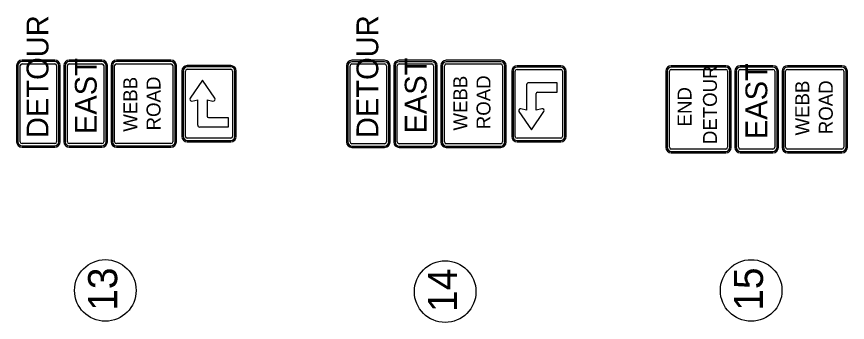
# Model space of a CAD drawing. Extents: x 1123038 to 1172987, y 554419 to 623636.
# Drawn here: x 1129459 to 1134226, y 558025 to 559782 of the extents above; entities that cross this region are included whole.
import ezdxf

# ---------------------------------------------------------------- set-up
doc = ezdxf.new("R2010")
doc.units = 0
doc.layers.add('D_Text_Standard', color=7, linetype='Continuous')
doc.layers.add('Default', color=7, linetype='Continuous')

msp = doc.modelspace()

# ---------------------------------------------------------------- linework, layer by layer
at = {"layer": 'D_Text_Standard'}
for centre in [(1129968.3, 558209), (1131918.2, 558202.3), (1133674, 558208.9)]:
    msp.add_circle(centre, 176.8, dxfattribs=at)
at = {"layer": 'Default'}
for p, q in [((1129677.9, 559531.6), (1129490.4, 559531.6)), ((1129677.9, 559523.8), (1129490.4, 559523.8)), ((1129490.4, 559510.8), (1129677.9, 559510.8)), ((1129948.7, 559531.6), (1129761.2, 559531.6)), ((1129948.7, 559523.8), (1129761.2, 559523.8)), ((1129761.2, 559510.8), (1129948.7, 559510.8)), ((1130344.6, 559531.6), (1130032.1, 559531.6)), ((1130344.6, 559523.8), (1130032.1, 559523.8)), ((1130032.1, 559510.8), (1130344.6, 559510.8)), ((1131570.7, 559530.8), (1131383.2, 559530.8)), ((1131570.7, 559523), (1131383.2, 559523)), ((1131383.2, 559510), (1131570.7, 559510)), ((1131841.5, 559530.8), (1131654, 559530.8)), ((1131841.5, 559523), (1131654, 559523)), ((1131654, 559510), (1131841.5, 559510)), ((1132237.3, 559530.8), (1131924.8, 559530.8)), ((1132237.3, 559523), (1131924.8, 559523)), ((1131924.8, 559510), (1132237.3, 559510)), ((1129459.2, 559500.3), (1129459.2, 559062.9)), ((1129467, 559500.3), (1129467, 559062.9)), ((1129480, 559062.9), (1129480, 559500.3)), ((1129688.3, 559500.3), (1129688.3, 559062.9)), ((1129701.3, 559062.9), (1129701.3, 559500.3)), ((1129709.2, 559062.9), (1129709.2, 559500.3)), ((1129730, 559500.3), (1129730, 559062.9)), ((1129737.8, 559500.3), (1129737.8, 559062.9)), ((1129750.8, 559062.9), (1129750.8, 559500.3)), ((1129959.2, 559500.3), (1129959.2, 559062.9)), ((1129972.2, 559062.9), (1129972.2, 559500.3)), ((1129980, 559062.9), (1129980, 559500.3)), ((1130000.8, 559500.3), (1130000.8, 559062.9)), ((1130008.6, 559500.3), (1130008.6, 559062.9)), ((1130021.7, 559062.9), (1130021.7, 559500.3)), ((1130355, 559500.3), (1130355, 559062.9)), ((1130368, 559062.9), (1130368, 559500.3)), ((1130375.8, 559062.9), (1130375.8, 559500.3)), ((1130407.1, 559469.1), (1130407.1, 559094.1)), ((1130414.9, 559469.1), (1130414.9, 559094.1)), ((1130427.9, 559094.1), (1130427.9, 559469.1)), ((1130688.3, 559500.3), (1130438.3, 559500.3)), ((1130688.3, 559492.5), (1130438.3, 559492.5)), ((1130438.3, 559479.5), (1130688.3, 559479.5)), ((1130698.7, 559469.1), (1130698.7, 559094.1)), ((1130711.8, 559094.1), (1130711.8, 559469.1)), ((1130719.6, 559094.1), (1130719.6, 559469.1)), ((1131351.9, 559499.5), (1131351.9, 559062)), ((1131359.7, 559499.5), (1131359.7, 559062)), ((1131372.8, 559062), (1131372.8, 559499.5)), ((1131581.1, 559499.5), (1131581.1, 559062)), ((1131594.1, 559062), (1131594.1, 559499.5)), ((1131601.9, 559062), (1131601.9, 559499.5)), ((1131622.8, 559499.5), (1131622.8, 559062)), ((1131630.6, 559499.5), (1131630.6, 559062)), ((1131643.6, 559062), (1131643.6, 559499.5)), ((1131851.9, 559499.5), (1131851.9, 559062)), ((1131865, 559062), (1131865, 559499.5)), ((1131872.8, 559062), (1131872.8, 559499.5)), ((1131893.6, 559499.5), (1131893.6, 559062)), ((1131901.4, 559499.5), (1131901.4, 559062)), ((1131914.4, 559062), (1131914.4, 559499.5)), ((1132247.8, 559499.5), (1132247.8, 559062)), ((1132260.8, 559062), (1132260.8, 559499.5)), ((1132268.6, 559062), (1132268.6, 559499.5)), ((1132299.8, 559468.3), (1132299.8, 559093.3)), ((1132307.7, 559468.3), (1132307.7, 559093.3)), ((1132320.7, 559093.3), (1132320.7, 559468.3)), ((1132581.1, 559499.5), (1132331.1, 559499.5)), ((1132581.1, 559491.7), (1132331.1, 559491.7)), ((1132331.1, 559478.7), (1132581.1, 559478.7)), ((1132591.5, 559468.3), (1132591.5, 559093.3)), ((1132604.5, 559093.3), (1132604.5, 559468.3)), ((1132612.3, 559093.3), (1132612.3, 559468.3)), ((1133184.5, 559468.5), (1133184.5, 559031)), ((1133192.3, 559468.5), (1133192.3, 559031)), ((1133205.3, 559031), (1133205.3, 559468.5)), ((1133528.2, 559499.7), (1133215.7, 559499.7)), ((1133528.2, 559491.9), (1133215.7, 559491.9)), ((1133215.7, 559478.9), (1133528.2, 559478.9)), ((1133538.7, 559468.5), (1133538.7, 559031)), ((1133551.7, 559031), (1133551.7, 559468.5)), ((1133559.5, 559031), (1133559.5, 559468.5)), ((1133580.3, 559468.5), (1133580.3, 559031)), ((1133588.1, 559468.5), (1133588.1, 559031)), ((1133601.2, 559031), (1133601.2, 559468.5)), ((1133799.1, 559499.7), (1133611.6, 559499.7)), ((1133799.1, 559491.9), (1133611.6, 559491.9)), ((1133611.6, 559478.9), (1133799.1, 559478.9)), ((1133809.5, 559468.5), (1133809.5, 559031)), ((1133822.5, 559031), (1133822.5, 559468.5)), ((1133830.3, 559031), (1133830.3, 559468.5)), ((1133851.2, 559468.5), (1133851.2, 559031)), ((1133859, 559468.5), (1133859, 559031)), ((1133872, 559031), (1133872, 559468.5)), ((1134194.9, 559499.7), (1133882.4, 559499.7)), ((1134194.9, 559491.9), (1133882.4, 559491.9)), ((1133882.4, 559478.9), (1134194.9, 559478.9)), ((1134205.3, 559468.5), (1134205.3, 559031)), ((1134218.3, 559031), (1134218.3, 559468.5)), ((1134226.2, 559031), (1134226.2, 559468.5)), ((1130525.6, 559416.4), (1130454.3, 559312.6)), ((1130596.9, 559312.6), (1130525.6, 559416.4)), ((1132385.8, 559390.2), (1132385.8, 559244.3)), ((1132561.6, 559401.9), (1132397.5, 559401.9)), ((1132561.6, 559347.2), (1132561.6, 559401.9)), ((1132440.5, 559244.3), (1132440.5, 559339.4)), ((1132448.3, 559347.2), (1132561.6, 559347.2)), ((1130465.4, 559296.8), (1130498.2, 559304.4)), ((1130498.2, 559158.6), (1130498.2, 559304.4)), ((1130552.9, 559304.4), (1130585.7, 559296.8)), ((1130552.9, 559304.4), (1130552.9, 559209.3)), ((1132341.8, 559236.2), (1132413.1, 559132.4)), ((1132385.8, 559244.3), (1132353, 559251.9)), ((1132413.1, 559132.4), (1132484.4, 559236.2)), ((1132473.3, 559251.9), (1132440.5, 559244.3)), ((1130560.7, 559201.5), (1130674, 559201.5)), ((1130674, 559201.5), (1130674, 559146.8)), ((1130674, 559146.8), (1130509.9, 559146.8)), ((1130688.3, 559083.7), (1130438.3, 559083.7)), ((1132581.1, 559082.9), (1132331.1, 559082.9)), ((1129677.9, 559052.4), (1129490.4, 559052.4)), ((1129490.4, 559039.4), (1129677.9, 559039.4)), ((1129490.4, 559031.6), (1129677.9, 559031.6)), ((1129948.7, 559052.4), (1129761.2, 559052.4)), ((1129761.2, 559039.4), (1129948.7, 559039.4)), ((1129761.2, 559031.6), (1129948.7, 559031.6)), ((1130344.6, 559052.4), (1130032.1, 559052.4)), ((1130032.1, 559039.4), (1130344.6, 559039.4)), ((1130032.1, 559031.6), (1130344.6, 559031.6)), ((1130438.3, 559070.7), (1130688.3, 559070.7)), ((1130438.3, 559062.9), (1130688.3, 559062.9)), ((1131570.7, 559051.6), (1131383.2, 559051.6)), ((1131383.2, 559038.6), (1131570.7, 559038.6)), ((1131383.2, 559030.8), (1131570.7, 559030.8)), ((1131841.5, 559051.6), (1131654, 559051.6)), ((1131654, 559038.6), (1131841.5, 559038.6)), ((1131654, 559030.8), (1131841.5, 559030.8)), ((1132237.3, 559051.6), (1131924.8, 559051.6)), ((1131924.8, 559038.6), (1132237.3, 559038.6)), ((1131924.8, 559030.8), (1132237.3, 559030.8)), ((1132331.1, 559069.9), (1132581.1, 559069.9)), ((1132331.1, 559062), (1132581.1, 559062)), ((1133528.2, 559020.6), (1133215.7, 559020.6)), ((1133215.7, 559007.5), (1133528.2, 559007.5)), ((1133215.7, 558999.7), (1133528.2, 558999.7)), ((1133799.1, 559020.6), (1133611.6, 559020.6)), ((1133611.6, 559007.5), (1133799.1, 559007.5)), ((1133611.6, 558999.7), (1133799.1, 558999.7)), ((1134194.9, 559020.6), (1133882.4, 559020.6)), ((1133882.4, 559007.5), (1134194.9, 559007.5)), ((1133882.4, 558999.7), (1134194.9, 558999.7))]:
    msp.add_line(p, q, dxfattribs=at)
for centre, radius, start, end in [((1129490.4, 559500.3), 31.2, 90, 180), ((1129490.4, 559500.3), 23.4, 90, 180), ((1129490.4, 559500.3), 10.4, 90, 180), ((1129677.9, 559500.3), 31.2, 0, 90), ((1129677.9, 559500.3), 23.4, 0, 90), ((1129677.9, 559500.3), 10.4, 0, 90), ((1129761.2, 559500.3), 31.2, 90, 180), ((1129761.2, 559500.3), 23.4, 90, 180), ((1129761.2, 559500.3), 10.4, 90, 180), ((1129948.7, 559500.3), 31.2, 0, 90), ((1129948.7, 559500.3), 23.4, 0, 90), ((1129948.7, 559500.3), 10.4, 0, 90), ((1130032.1, 559500.3), 31.2, 90, 180), ((1130032.1, 559500.3), 23.4, 90, 180), ((1130032.1, 559500.3), 10.4, 90, 180), ((1130344.6, 559500.3), 31.2, 0, 90), ((1130344.6, 559500.3), 23.4, 0, 90), ((1130344.6, 559500.3), 10.4, 0, 90), ((1131383.2, 559499.5), 31.2, 90, 180), ((1131383.2, 559499.5), 23.4, 90, 180), ((1131383.2, 559499.5), 10.4, 90, 180), ((1131570.7, 559499.5), 31.2, 0, 90), ((1131570.7, 559499.5), 23.4, 0, 90), ((1131570.7, 559499.5), 10.4, 0, 90), ((1131654, 559499.5), 31.2, 90, 180), ((1131654, 559499.5), 23.4, 90, 180), ((1131654, 559499.5), 10.4, 90, 180), ((1131841.5, 559499.5), 31.2, 0, 90), ((1131841.5, 559499.5), 23.4, 0, 90), ((1131841.5, 559499.5), 10.4, 0, 90), ((1131924.8, 559499.5), 31.2, 90, 180), ((1131924.8, 559499.5), 23.4, 90, 180), ((1131924.8, 559499.5), 10.4, 90, 180), ((1132237.3, 559499.5), 31.2, 0, 90), ((1132237.3, 559499.5), 23.4, 0, 90), ((1132237.3, 559499.5), 10.4, 0, 90), ((1130438.3, 559469.1), 31.2, 90, 180), ((1130438.3, 559469.1), 23.4, 90, 180), ((1130438.3, 559469.1), 10.4, 90, 180), ((1130688.3, 559469.1), 31.2, 0, 90), ((1130688.3, 559469.1), 23.4, 0, 90), ((1130688.3, 559469.1), 10.4, 0, 90), ((1132331.1, 559468.3), 31.2, 90, 180), ((1132331.1, 559468.3), 23.4, 90, 180), ((1132331.1, 559468.3), 10.4, 90, 180), ((1132581.1, 559468.3), 31.2, 0, 90), ((1132581.1, 559468.3), 23.4, 0, 90), ((1132581.1, 559468.3), 10.4, 0, 90), ((1133215.7, 559468.5), 31.2, 90, 180), ((1133215.7, 559468.5), 23.4, 90, 180), ((1133215.7, 559468.5), 10.4, 90, 180), ((1133528.2, 559468.5), 31.2, 0, 90), ((1133528.2, 559468.5), 23.4, 0, 90), ((1133528.2, 559468.5), 10.4, 0, 90), ((1133611.6, 559468.5), 31.2, 90, 180), ((1133611.6, 559468.5), 23.4, 90, 180), ((1133611.6, 559468.5), 10.4, 90, 180), ((1133799.1, 559468.5), 31.2, 0, 90), ((1133799.1, 559468.5), 23.4, 0, 90), ((1133799.1, 559468.5), 10.4, 0, 90), ((1133882.4, 559468.5), 31.2, 90, 180), ((1133882.4, 559468.5), 23.4, 90, 180), ((1133882.4, 559468.5), 10.4, 90, 180), ((1134194.9, 559468.5), 31.2, 0, 90), ((1134194.9, 559468.5), 23.4, 0, 90), ((1134194.9, 559468.5), 10.4, 0, 90), ((1132397.5, 559390.2), 11.7, 90, 180), ((1130463.1, 559307), 10.4, 147.7244, 282.9503), ((1130588.1, 559307), 10.4, 257.0497, 32.2757), ((1132448.3, 559339.4), 7.81, 90, 180), ((1132350.6, 559241.7), 10.4, 77.0497, 212.2757), ((1132475.6, 559241.7), 10.4, 327.7244, 102.9504), ((1130560.7, 559209.3), 7.81, 180, 270), ((1130509.9, 559158.6), 11.7, 180, 270), ((1130438.3, 559094.1), 31.2, 180, 270), ((1130438.3, 559094.1), 23.4, 180, 270), ((1130438.3, 559094.1), 10.4, 180, 270), ((1130688.3, 559094.1), 31.2, 270, 0), ((1130688.3, 559094.1), 23.4, 270, 0), ((1130688.3, 559094.1), 10.4, 270, 0), ((1132331.1, 559093.3), 31.2, 180, 270), ((1132331.1, 559093.3), 23.4, 180, 270), ((1132331.1, 559093.3), 10.4, 180, 270), ((1132581.1, 559093.3), 31.2, 270, 0), ((1132581.1, 559093.3), 23.4, 270, 0), ((1132581.1, 559093.3), 10.4, 270, 0), ((1129490.4, 559062.9), 31.2, 180, 270), ((1129490.4, 559062.9), 23.4, 180, 270), ((1129490.4, 559062.9), 10.4, 180, 270), ((1129677.9, 559062.9), 31.2, 270, 0), ((1129677.9, 559062.9), 23.4, 270, 0), ((1129677.9, 559062.9), 10.4, 270, 0), ((1129761.2, 559062.9), 31.2, 180, 270), ((1129761.2, 559062.9), 23.4, 180, 270), ((1129761.2, 559062.9), 10.4, 180, 270), ((1129948.7, 559062.9), 31.2, 270, 0), ((1129948.7, 559062.9), 23.4, 270, 0), ((1129948.7, 559062.9), 10.4, 270, 0), ((1130032.1, 559062.9), 31.2, 180, 270), ((1130032.1, 559062.9), 23.4, 180, 270), ((1130032.1, 559062.9), 10.4, 180, 270), ((1130344.6, 559062.9), 31.2, 270, 0), ((1130344.6, 559062.9), 23.4, 270, 0), ((1130344.6, 559062.9), 10.4, 270, 0), ((1131383.2, 559062), 31.2, 180, 270), ((1131383.2, 559062), 23.4, 180, 270), ((1131383.2, 559062), 10.4, 180, 270), ((1131570.7, 559062), 31.2, 270, 0), ((1131570.7, 559062), 23.4, 270, 0), ((1131570.7, 559062), 10.4, 270, 0), ((1131654, 559062), 31.2, 180, 270), ((1131654, 559062), 23.4, 180, 270), ((1131654, 559062), 10.4, 180, 270), ((1131841.5, 559062), 31.2, 270, 0), ((1131841.5, 559062), 23.4, 270, 0), ((1131841.5, 559062), 10.4, 270, 0), ((1131924.8, 559062), 31.2, 180, 270), ((1131924.8, 559062), 23.4, 180, 270), ((1131924.8, 559062), 10.4, 180, 270), ((1132237.3, 559062), 31.2, 270, 0), ((1132237.3, 559062), 23.4, 270, 0), ((1132237.3, 559062), 10.4, 270, 0), ((1133215.7, 559031), 31.2, 180, 270), ((1133215.7, 559031), 23.4, 180, 270), ((1133215.7, 559031), 10.4, 180, 270), ((1133528.2, 559031), 31.2, 270, 0), ((1133528.2, 559031), 23.4, 270, 0), ((1133528.2, 559031), 10.4, 270, 0), ((1133611.6, 559031), 31.2, 180, 270), ((1133611.6, 559031), 23.4, 180, 270), ((1133611.6, 559031), 10.4, 180, 270), ((1133799.1, 559031), 31.2, 270, 0), ((1133799.1, 559031), 23.4, 270, 0), ((1133799.1, 559031), 10.4, 270, 0), ((1133882.4, 559031), 31.2, 180, 270), ((1133882.4, 559031), 23.4, 180, 270), ((1133882.4, 559031), 10.4, 180, 270), ((1134194.9, 559031), 31.2, 270, 0), ((1134194.9, 559031), 23.4, 270, 0), ((1134194.9, 559031), 10.4, 270, 0)]:
    msp.add_arc(centre, radius, start, end, dxfattribs=at)

# ---------------------------------------------------------------- texts
at = {"layer": 'D_Text_Standard'}
for s, p in [('13', (1130036.3, 558092.3)), ('14', (1131986.1, 558085.6)), ('15', (1133741.8, 558092.3))]:
    msp.add_text(s, height=167.06, rotation=90, dxfattribs=at).set_placement(p)
at = {"layer": 'Default'}
for s, height, p in [('DETOUR', 125, (1129641.6, 559083.9)), ('DETOUR', 125, (1131534.3, 559083.8)), ('EAST', 125, (1129918.6, 559106.9)), ('EAST', 125, (1131811.4, 559110.2)), ('EAST', 125, (1133766.4, 559077.8)), ('DETOUR', 80, (1133477.6, 559049.5)), ('WEBB', 80, (1130151.4, 559120.6)), ('ROAD', 80, (1130284.8, 559128.2)), ('WEBB', 80, (1132044.9, 559127.1)), ('ROAD', 80, (1132178.2, 559135.1)), ('WEBB', 80, (1134007.2, 559099.2)), ('ROAD', 80, (1134142.2, 559106.4)), ('END', 80, (1133331.8, 559151))]:
    msp.add_text(s, height=height, rotation=90, dxfattribs=at).set_placement(p)

doc.saveas('drawing.dxf')
